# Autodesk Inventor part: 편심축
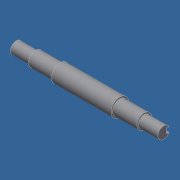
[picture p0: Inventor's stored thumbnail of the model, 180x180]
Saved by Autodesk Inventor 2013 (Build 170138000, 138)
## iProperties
Created: 2014-12
Part Number: 편심축
Material: Generic
Document SubType Name: Modeling
Designer: CAD-B31
Density: 1 g/cm^3
Author: CAD-B31
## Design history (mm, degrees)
sketch "스케치1"
  geometry: L1 (-75.5, 0)-(75.5, 0); L2 (-75.5, 0)-(-75.5, 6); L3 (-75.5, 6)-(-55.5, 6); L4 (-55.5, 6)-(-55.5, 7.5); L5 (-55.5, 7.5)-(-30.5, 7.5); L6 (-30.5, 7.5)-(-30.5, 9); L7 (-30.5, 9)-(30.5, 9); L8 (30.5, 9)-(30.5, 7.5); L9 (30.5, 7.5)-(55.5, 7.5); L10 (55.5, 7.5)-(55.5, 6); L11 (55.5, 6)-(75.5, 6); L12 (75.5, 6)-(75.5, 0); L13 (-75.5, 6)-(-61.5, 6); L14 (-61.5, 6)-(-61.5, 3); L15 (-61.5, 3)-(-75.5, 3); L16 (-75.5, 3)-(-75.5, 6); L17 (61.5, 6)-(75.5, 6); L18 (75.5, 6)-(75.5, 3); L19 (75.5, 3)-(61.5, 3); L20 (61.5, 3)-(61.5, 6); 2 further points
  constraints: 40 end point, 11 parallel, 5 perpendicular, 3 horizontal, 2 midpoint, 1 coincident, 1 collinear, 1 point on line
  dimensions: "d0" = 151 distance of L1.start L1.end; "d2" = 12 diameter of L3 L1; "d3" = 12 diameter of L11 L1; "d4" = 15 diameter of L5 L1; "d5" = 15 diameter of L9 L1; "d6" = 18 diameter of L7 L1; "d7" = 20 distance of L2.end L3.end; "d8" = 25 distance of L4.end L5.end; "d9" = 20 distance of L10.end L11.end; "d10" = 25 distance of L8.end L9.end; "d11" = 3 distance of L19.end L17.start (derived); "d12" = 3 distance of L13.end L14.end; "d13" = 14 distance of L14.end L15.end; "d14" = 14 distance of L18.end L19.end
revolve "회전1" stored, may be unused: angle "d15" = 90 deg
extrude "돌출1" cut sketch "스케치1" stored distance "d16" = 5; taper "d17" = 0 deg
extrude "돌출2" cut sketch "스케치1" stored distance "d18" = 5; taper "d19" = 0 deg
fillet "모깎기1" dims "d20" = 2.5
node "솔리드1"
